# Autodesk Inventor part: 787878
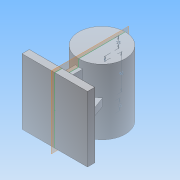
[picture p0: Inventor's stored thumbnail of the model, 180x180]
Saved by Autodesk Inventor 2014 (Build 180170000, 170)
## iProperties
Created: 2019-06
Part Number: 787878
Material: 일반
Document SubType Name: Modeling
Designer: NET
Density: 1 g/cm^3
Appearance: 기본값
Author: NET
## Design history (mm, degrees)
sketch "스케치3"
  geometry: L1 (-45, 45)-(45, 45); L2 (45, 45)-(45, -45); L3 (45, -45)-(-45, -45); L4 (-45, -45)-(-45, 45); L5 (-45, 45)-(45, -45); L6 (45, 45)-(-45, -45); 1 further point
  constraints: 12 end point, 2 midpoint, 2 parallel, 1 horizontal, 1 perpendicular
  dimensions: "d5" = 90 distance of L2.end L3.end; "d6" = 90 distance of L1.end L2.end
extrude "돌출2" new body sketch "스케치3" distance "d7" = 10; taper "d8" = 0 deg
node "작업 평면1"
sketch "스케치4"
  geometry: L1 (0, 0)-(0, 10) reference; L2 (0, 10)-(90, 10) reference; L3 (90, 10)-(90, 0) reference; L4 (90, 0)-(0, 0) reference; L5 (45, 0)-(45, 65); L6 (0, 65)-(90, 65); L7 (0, 65)-(0, 97); L8 (0, 97)-(90, 97); L9 (90, 97)-(90, 65)
  constraints: 10 end point, 3 perpendicular, 1 horizontal, 1 midpoint, 1 parallel
  dimensions: "d9" = 65 distance of L5.end L5.start; "d10" = 90 distance of L6.start L6.end; "d11" = 64 diameter of L8 L6
revolve "회전1" sketch "스케치4" stored, may be unused: angle "d12" = 90 deg
sketch "스케치5"
  geometry: L1 (-45, -45)-(45, -45) reference; L2 (-45, 45)-(-45, -45) reference; L3 (-45, -45)-(-45, 45) reference; L4 (-45, 45)-(45, 45) reference; L5 (45, 45)-(45, -45) reference; L6 (45, -45)-(-45, -45) reference; L7 (-5, -35)-(5, -35); L8 (5, -35)-(5, 35); L9 (5, 35)-(-5, 35); L10 (-5, 35)-(-5, -35); 5 further points
  constraints: 8 end point, 4 midpoint, 2 parallel, 1 horizontal, 1 horizontal alignment, 1 perpendicular, 1 vertical alignment
  dimensions: "d13" = 10 distance of L8.end L9.end; "d14" = 70 distance of L9.end L7.start
extrude "돌출3" join sketch "스케치5" stored distance "d15" = 10; taper "d16" = 0 deg
node "작업 평면2"
sketch "스케치6"
  geometry: L1 (90, 10)-(90, 0) reference; L2 (90, 0)-(0, 0) reference; L3 (0, 0)-(0, 10) reference; L4 (0, 10)-(40, 10) reference; L5 (40, 10)-(40, 33.393) reference; L6 (50, 33.393)-(50, 10) reference; L7 (50, 10)-(90, 10) reference; L8 (10, 10)-(21.942, 42.811); A1 r 32 centre (45, 65) between (50, 33.393) and (40, 33.393) reference; 1 further point
  constraints: 2 end point, 1 point on circle, 1 point on line
  dimensions: "d17" = 110 deg angle of L4 L8; "d18" = 10 distance of L3.end L8.start
feature "리브1" sketch "스케치6" dims "d19" = 1, "d20" = 10, "d21" = 0, "d22" = 0, "d23" = 1, "d24" = 1
node "작업 평면3"
sketch "스케치7"
  geometry: L1 (80, 10)-(90, 10) reference; L2 (90, 10)-(90, 0) reference; L3 (90, 0)-(0, 0) reference; L4 (0, 0)-(0, 10) reference; L5 (0, 10)-(10, 10) reference; L6 (10, 10)-(10, 33) reference; L7 (10, 33)-(0, 33) reference; L8 (0, 33)-(0, 97) reference; L9 (0, 97)-(90, 97) reference; L10 (90, 97)-(90, 33) reference; L11 (90, 33)-(80, 33) reference; L12 (80, 33)-(80, 10) reference; L13 (0, 65)-(90, 65); L14 (0, 82.087)-(15, 82.087); L15 (15, 82.087)-(15, 77.306); L16 (15, 77.306)-(21, 77.306); L17 (21, 77.306)-(21, 85.879); L18 (21, 85.879)-(69, 85.879); L19 (69, 85.879)-(69, 77.306); L20 (69, 77.306)-(75, 77.306); L21 (75, 77.306)-(75, 82.912); L22 (75, 82.912)-(90, 82.912); 1 further point
  constraints: 20 end point, 7 parallel, 2 midpoint, 2 perpendicular, 2 point on line
  dimensions: "d25" = 15 distance of L21.end L22.end; "d26" = 15 distance of L14.start L14.end; "d27" = 48 distance of L17.end L18.end; "d28" = 6 distance of L15.end L16.end
  node "절단 모서리 투영4"
node "솔리드2"
mirror "대칭1"
node "절단 모서리 투영1"
node "절단 모서리 투영2"
node "절단 모서리 투영3"
